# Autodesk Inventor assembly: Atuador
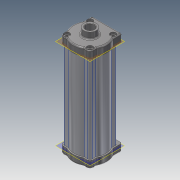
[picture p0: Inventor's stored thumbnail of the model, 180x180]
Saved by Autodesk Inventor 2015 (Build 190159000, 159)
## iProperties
Created: 2015-04
Part Number: Atuador
Document SubType Name: Assembly
Designer: TREINA6
Author: TREINA6
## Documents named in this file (4)
- C:\Users\Andrew Almeida\Documents\Projeto WS2015\WS2015 CAD Data ANLAS\01\Pneumatic System\Atuador.iam
- C:\Users\Andrew Almeida\Documents\Projeto WS2015\WS2015 CAD Data ANLAS\01\Pneumatic System\Corpo_Atuador.ipt
- C:\Users\Andrew Almeida\Documents\Projeto WS2015\WS2015 CAD Data ANLAS\01\Pneumatic System\Suporte_Atuador.ipt
- C:\Users\Andrew Almeida\Documents\Projeto WS2015\WS2015 CAD Data ANLAS\01\Pneumatic System\Suporte_Atuador2.ipt
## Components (3 placed, 3 different names)
1. Corpo_Atuador:1 — Flush:1, Flush:2, Insert:1, Mate:1
2. Suporte_Atuador:1 — Flush:1, Flush:2
3. Suporte_Atuador2:1 — Insert:1, Mate:1
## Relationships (4: Flush 2, Insert 1, Mate 1)
- Flush:1: Corpo_Atuador:1 ↔ Suporte_Atuador:1
- Flush:2: Corpo_Atuador:1 ↔ Suporte_Atuador:1
- Insert:1: Corpo_Atuador:1 ↔ Suporte_Atuador2:1
- Mate:1: Corpo_Atuador:1 ↔ Suporte_Atuador2:1
